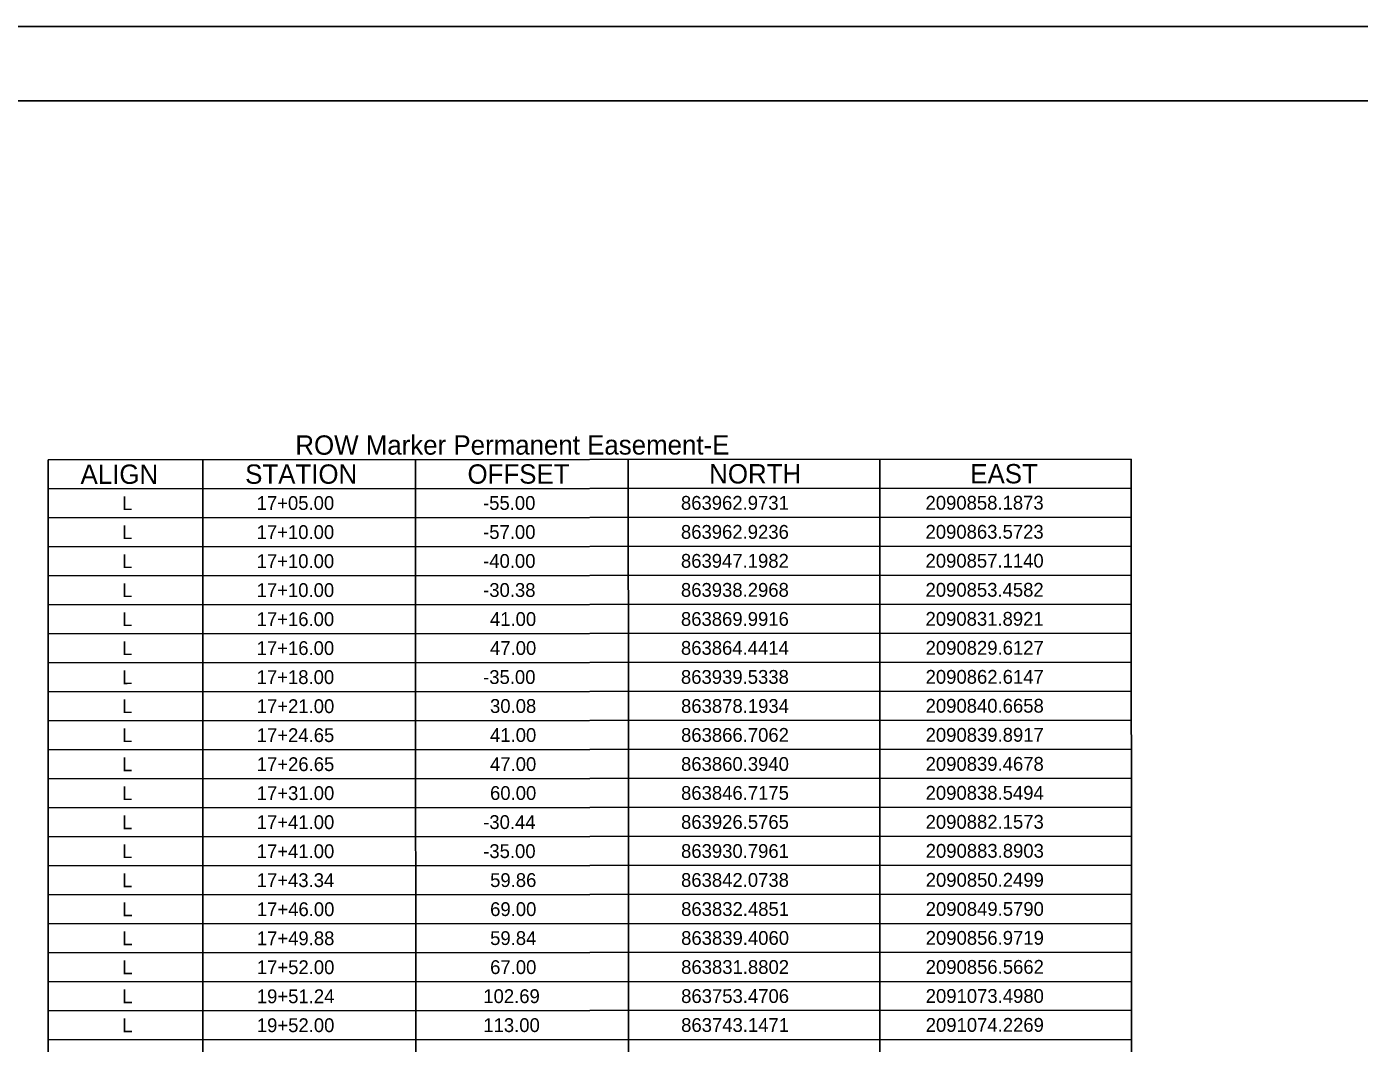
# Model space of a CAD drawing. Extents: x 2093228 to 2098328, y 861854 to 865154.
# Drawn here: x 2094038 to 2095387, y 864125 to 865154 of the extents above; entities that cross this region are included whole.
import ezdxf

# ---------------------------------------------------------------- set-up
doc = ezdxf.new("R2010")
doc.units = 0
for name, color, linetype in [('CTL Sheet Notes CELL', 7, 'Continuous'), ('CTL Sheet Table Cell', 7, 'Continuous'), ('CTL Sheet Text', 7, 'Continuous'), ('Sheet Plan CELL', 7, 'Continuous'), ('Sheet Plot Border Inside CELL', 7, 'Continuous')]:
    doc.layers.add(name, color=color, linetype=linetype)

msp = doc.modelspace()

# ---------------------------------------------------------------- linework, layer by layer
at = {"layer": 'CTL Sheet Table Cell'}
for p, q in [((2094059.8, 864715.8), (2095155.9, 864716.3)), ((2094059.8, 864715.8), (2094059.8, 864686.4)), ((2094216.3, 864715.9), (2094216.4, 864686.5)), ((2094431.7, 864716), (2094431.7, 864686.6)), ((2094647, 864716.1), (2094647, 864686.7)), ((2094901.4, 864716.2), (2094901.5, 864686.8)), ((2095155.9, 864716.3), (2095155.9, 864687)), ((2094059.8, 864686.4), (2095155.9, 864687)), ((2094059.8, 864686.4), (2094059.8, 864657.1)), ((2094216.4, 864686.5), (2094216.4, 864657.2)), ((2094431.7, 864686.6), (2094431.7, 864657.3)), ((2094647, 864686.7), (2094647, 864657.4)), ((2094901.5, 864686.8), (2094901.5, 864657.5)), ((2095155.9, 864687), (2095155.9, 864657.6)), ((2094059.8, 864657.1), (2095155.9, 864657.6)), ((2094059.8, 864657.1), (2094059.8, 864627.7)), ((2094216.4, 864657.2), (2094216.4, 864627.8)), ((2094431.7, 864657.3), (2094431.7, 864627.9)), ((2094647, 864657.4), (2094647, 864628)), ((2094901.5, 864657.5), (2094901.5, 864628.1)), ((2095155.9, 864657.6), (2095156, 864628.2)), ((2094059.8, 864627.7), (2095156, 864628.2)), ((2094059.8, 864627.7), (2094059.8, 864598.4)), ((2094216.4, 864627.8), (2094216.4, 864598.4)), ((2094431.7, 864627.9), (2094431.7, 864598.5)), ((2094647, 864628), (2094647, 864598.6)), ((2094901.5, 864628.1), (2094901.5, 864598.8)), ((2095156, 864628.2), (2095156, 864598.9)), ((2094059.8, 864598.4), (2095156, 864598.9)), ((2094059.8, 864598.4), (2094059.8, 864569)), ((2094216.4, 864598.4), (2094216.4, 864569.1)), ((2094431.7, 864598.5), (2094431.7, 864569.2)), ((2094647, 864598.6), (2094647.1, 864569.3)), ((2094901.5, 864598.8), (2094901.5, 864569.4)), ((2095156, 864598.9), (2095156, 864569.5)), ((2094059.8, 864569), (2095156, 864569.5)), ((2094059.8, 864569), (2094059.8, 864539.6)), ((2094216.4, 864569.1), (2094216.4, 864539.7)), ((2094431.7, 864569.2), (2094431.7, 864539.8)), ((2094647.1, 864569.3), (2094647.1, 864539.9)), ((2094901.5, 864569.4), (2094901.5, 864540)), ((2095156, 864569.5), (2095156, 864540.2)), ((2094059.8, 864539.6), (2095156, 864540.2)), ((2094431.7, 864539.8), (2094431.8, 864510.4)), ((2094647.1, 864539.9), (2094647.1, 864510.6)), ((2094901.5, 864540), (2094901.5, 864510.7)), ((2095156, 864540.2), (2095156, 864510.8)), ((2094059.8, 864539.6), (2094059.9, 864510.3)), ((2094216.4, 864539.7), (2094216.4, 864510.3)), ((2094059.9, 864510.3), (2095156, 864510.8)), ((2094059.9, 864510.3), (2094059.9, 864480.9)), ((2094216.4, 864510.3), (2094216.5, 864481)), ((2094431.8, 864510.4), (2094431.8, 864481.1)), ((2094647.1, 864510.6), (2094647.1, 864481.2)), ((2094901.5, 864510.7), (2094901.6, 864481.3)), ((2095156, 864510.8), (2095156, 864481.4)), ((2094059.9, 864480.9), (2095156, 864481.4)), ((2094059.9, 864480.9), (2094059.9, 864451.5)), ((2094216.5, 864481), (2094216.5, 864451.6)), ((2094431.8, 864481.1), (2094431.8, 864451.7)), ((2094647.1, 864481.2), (2094647.1, 864451.8)), ((2094901.6, 864481.3), (2094901.6, 864452)), ((2095156, 864481.4), (2095156, 864452.1)), ((2094059.9, 864451.5), (2095156, 864452.1)), ((2094059.9, 864451.5), (2094059.9, 864422.2)), ((2094216.5, 864451.6), (2094216.5, 864422.3)), ((2094431.8, 864451.7), (2094431.8, 864422.4)), ((2094647.1, 864451.8), (2094647.1, 864422.5)), ((2094901.6, 864452), (2094901.6, 864422.6)), ((2095156, 864452.1), (2095156.1, 864422.7)), ((2094059.9, 864422.2), (2095156.1, 864422.7)), ((2094059.9, 864422.2), (2094059.9, 864392.8)), ((2094216.5, 864422.3), (2094216.5, 864392.9)), ((2094431.8, 864422.4), (2094431.8, 864393)), ((2094647.1, 864422.5), (2094647.1, 864393.1)), ((2094901.6, 864422.6), (2094901.6, 864393.2)), ((2095156.1, 864422.7), (2095156.1, 864393.4)), ((2094059.9, 864392.8), (2095156.1, 864393.4)), ((2094059.9, 864392.8), (2094059.9, 864363.5)), ((2094216.5, 864392.9), (2094216.5, 864363.5)), ((2094431.8, 864393), (2094431.8, 864363.6)), ((2094647.1, 864393.1), (2094647.2, 864363.7)), ((2094901.6, 864393.2), (2094901.6, 864363.9)), ((2095156.1, 864393.4), (2095156.1, 864364)), ((2094059.9, 864363.5), (2095156.1, 864364)), ((2094059.9, 864363.5), (2094059.9, 864334.1)), ((2094216.5, 864363.5), (2094216.5, 864334.2)), ((2094431.8, 864363.6), (2094431.8, 864334.3)), ((2094647.2, 864363.7), (2094647.2, 864334.4)), ((2094901.6, 864363.9), (2094901.6, 864334.5)), ((2095156.1, 864364), (2095156.1, 864334.6)), ((2094059.9, 864334.1), (2095156.1, 864334.6)), ((2094059.9, 864334.1), (2094059.9, 864304.7)), ((2094216.5, 864334.2), (2094216.5, 864304.8)), ((2094431.8, 864334.3), (2094431.9, 864304.9)), ((2094647.2, 864334.4), (2094647.2, 864305)), ((2094901.6, 864334.5), (2094901.6, 864305.1)), ((2095156.1, 864334.6), (2095156.1, 864305.3)), ((2094059.9, 864304.7), (2095156.1, 864305.3)), ((2094059.9, 864304.7), (2094060, 864275.4)), ((2094216.5, 864304.8), (2094216.6, 864275.5)), ((2094431.9, 864304.9), (2094431.9, 864275.6)), ((2094647.2, 864305), (2094647.2, 864275.7)), ((2094901.6, 864305.1), (2094901.7, 864275.8)), ((2095156.1, 864305.3), (2095156.1, 864275.9)), ((2094060, 864275.4), (2095156.1, 864275.9)), ((2094060, 864275.4), (2094060, 864246)), ((2094216.6, 864275.5), (2094216.6, 864246.1)), ((2094431.9, 864275.6), (2094431.9, 864246.2)), ((2094647.2, 864275.7), (2094647.2, 864246.3)), ((2094901.7, 864275.8), (2094901.7, 864246.4)), ((2095156.1, 864275.9), (2095156.1, 864246.5)), ((2094060, 864246), (2095156.1, 864246.5)), ((2094060, 864246), (2094060, 864216.7)), ((2094216.6, 864246.1), (2094216.6, 864216.7)), ((2094431.9, 864246.2), (2094431.9, 864216.8)), ((2094647.2, 864246.3), (2094647.2, 864216.9)), ((2094901.7, 864246.4), (2094901.7, 864217.1)), ((2095156.1, 864246.5), (2095156.2, 864217.2)), ((2094060, 864216.7), (2095156.2, 864217.2)), ((2094060, 864216.7), (2094060, 864187.3)), ((2094216.6, 864216.7), (2094216.6, 864187.4)), ((2094431.9, 864216.8), (2094431.9, 864187.5)), ((2094647.2, 864216.9), (2094647.2, 864187.6)), ((2094901.7, 864217.1), (2094901.7, 864187.7)), ((2095156.2, 864217.2), (2095156.2, 864187.8)), ((2094060, 864187.3), (2095156.2, 864187.8)), ((2094060, 864187.3), (2094060, 864157.9)), ((2094216.6, 864187.4), (2094216.6, 864158)), ((2094431.9, 864187.5), (2094431.9, 864158.1)), ((2094647.2, 864187.6), (2094647.3, 864158.2)), ((2094901.7, 864187.7), (2094901.7, 864158.3)), ((2095156.2, 864187.8), (2095156.2, 864158.5)), ((2094060, 864157.9), (2095156.2, 864158.5)), ((2094060, 864157.9), (2094060, 864128.6)), ((2094216.6, 864158), (2094216.6, 864128.6)), ((2094431.9, 864158.1), (2094431.9, 864128.7)), ((2094647.3, 864158.2), (2094647.3, 864128.9)), ((2094901.7, 864158.3), (2094901.7, 864129)), ((2095156.2, 864158.5), (2095156.2, 864129.1)), ((2094060, 864128.6), (2095156.2, 864129.1)), ((2094060, 864128.6), (2094060, 864099.2)), ((2094216.6, 864128.6), (2094216.6, 864099.3)), ((2094431.9, 864128.7), (2094432, 864099.4)), ((2094647.3, 864128.9), (2094647.3, 864099.5)), ((2094901.7, 864129), (2094901.7, 864099.6)), ((2095156.2, 864129.1), (2095156.2, 864099.7))]:
    msp.add_line(p, q, dxfattribs=at)
at = {"layer": 'Sheet Plan CELL'}
msp.add_lwpolyline([(2093753.4, 865079.1), (2098253.4, 865079.1), (2098253.4, 861929.1), (2093753.4, 861929.1)], close=True, dxfattribs=at)
at = {"layer": 'Sheet Plot Border Inside CELL'}
msp.add_lwpolyline([(2098328.4, 865154.1), (2093228.4, 865154.1), (2093228.4, 861854.1), (2098328.4, 861854.1)], close=True, dxfattribs=at)

# ---------------------------------------------------------------- texts
at = {"layer": 'CTL Sheet Notes CELL'}
for s, height, p in [('ROW Marker Permanent Easement-E', 19.574, (2094310.1, 864720.8)), ('ALIGN', 19.57, (2094092.7, 864691.3)), ('STATION', 19.57, (2094259.3, 864691.4)), ('OFFSET', 19.57, (2094484.3, 864691.5)), ('NORTH', 19.57, (2094728.9, 864691.7)), ('EAST', 19.57, (2094993.1, 864691.8))]:
    msp.add_text(s, height=height, rotation=0.0276, dxfattribs=at).set_placement(p)
at = {"layer": 'CTL Sheet Text'}
for s, height, p in [('L', 14, (2094134.7, 864664.8)), ('17+05.00', 13.98, (2094270.9, 864664.9)), ('-55.00', 13.98, (2094500, 864665)), ('863962.9731', 13.982, (2094700.3, 864665.1)), ('2090858.1873', 13.982, (2094947.8, 864665.2)), ('L', 14, (2094134.7, 864635.4)), ('17+10.00', 13.98, (2094270.9, 864635.5)), ('-57.00', 13.98, (2094500.1, 864635.6)), ('863962.9236', 13.982, (2094700.3, 864635.7)), ('2090863.5723', 13.982, (2094947.8, 864635.8)), ('2090857.1140', 13.982, (2094947.8, 864606.5)), ('L', 14, (2094134.7, 864606.1)), ('17+10.00', 13.98, (2094270.9, 864606.1)), ('-40.00', 13.98, (2094500.1, 864606.3)), ('863947.1982', 13.982, (2094700.3, 864606.4)), ('L', 14, (2094134.7, 864576.7)), ('17+10.00', 13.98, (2094270.9, 864576.8)), ('-30.38', 13.98, (2094500.1, 864576.9)), ('863938.2968', 13.982, (2094700.3, 864577)), ('2090853.4582', 13.982, (2094947.8, 864577.1)), ('L', 14, (2094134.7, 864547.4)), ('17+16.00', 13.98, (2094270.9, 864547.4)), ('41.00', 13.98, (2094507, 864547.5)), ('863869.9916', 13.982, (2094700.3, 864547.6)), ('2090831.8921', 13.982, (2094947.8, 864547.7)), ('L', 14, (2094134.7, 864518)), ('17+16.00', 13.98, (2094270.9, 864518.1)), ('47.00', 13.98, (2094507.1, 864518.2)), ('863864.4414', 13.982, (2094700.3, 864518.3)), ('2090829.6127', 13.982, (2094947.9, 864518.4)), ('L', 14, (2094134.7, 864488.6)), ('17+18.00', 13.98, (2094270.9, 864488.7)), ('-35.00', 13.98, (2094500.1, 864488.8)), ('863939.5338', 13.982, (2094700.3, 864488.9)), ('2090862.6147', 13.982, (2094947.9, 864489)), ('L', 14, (2094134.8, 864459.3)), ('17+21.00', 13.98, (2094271, 864459.3)), ('30.08', 13.98, (2094507.1, 864459.5)), ('863878.1934', 13.982, (2094700.4, 864459.5)), ('2090840.6658', 13.982, (2094947.9, 864459.7)), ('L', 14, (2094134.8, 864429.9)), ('17+24.65', 13.98, (2094271, 864430)), ('41.00', 13.98, (2094507.1, 864430.1)), ('863866.7062', 13.982, (2094700.4, 864430.2)), ('2090839.8917', 13.982, (2094947.9, 864430.3)), ('L', 14, (2094134.8, 864400.5)), ('17+26.65', 13.98, (2094271, 864400.6)), ('47.00', 13.98, (2094507.1, 864400.7)), ('863860.3940', 13.982, (2094700.4, 864400.8)), ('2090839.4678', 13.982, (2094947.9, 864400.9)), ('L', 14, (2094134.8, 864371.2)), ('17+31.00', 13.98, (2094271, 864371.3)), ('60.00', 13.98, (2094507.1, 864371.4)), ('863846.7175', 13.982, (2094700.4, 864371.5)), ('2090838.5494', 13.982, (2094947.9, 864371.6)), ('L', 14, (2094134.8, 864341.8)), ('17+41.00', 13.98, (2094271, 864341.9)), ('-30.44', 13.98, (2094500.2, 864342)), ('863926.5765', 13.982, (2094700.4, 864342.1)), ('2090882.1573', 13.982, (2094947.9, 864342.2)), ('L', 14, (2094134.8, 864312.5)), ('17+41.00', 13.98, (2094271, 864312.5)), ('-35.00', 13.98, (2094500.2, 864312.6)), ('863930.7961', 13.982, (2094700.4, 864312.7)), ('2090883.8903', 13.982, (2094948, 864312.9)), ('L', 14, (2094134.8, 864283.1)), ('17+43.34', 13.98, (2094271, 864283.2)), ('59.86', 13.98, (2094507.2, 864283.3)), ('863842.0738', 13.982, (2094700.4, 864283.4)), ('2090850.2499', 13.982, (2094948, 864283.5)), ('L', 14, (2094134.9, 864253.7)), ('17+46.00', 13.98, (2094271.1, 864253.8)), ('69.00', 13.98, (2094507.2, 864253.9)), ('863832.4851', 13.982, (2094700.5, 864254)), ('2090849.5790', 13.982, (2094948, 864254.1)), ('L', 14, (2094134.9, 864224.4)), ('17+49.88', 13.98, (2094271.1, 864224.4)), ('59.84', 13.98, (2094507.2, 864224.6)), ('863839.4060', 13.982, (2094700.5, 864224.7)), ('2090856.9719', 13.982, (2094948, 864224.8)), ('L', 14, (2094134.9, 864195)), ('17+52.00', 13.98, (2094271.1, 864195.1)), ('67.00', 13.98, (2094507.2, 864195.2)), ('863831.8802', 13.982, (2094700.5, 864195.3)), ('2090856.5662', 13.982, (2094948, 864195.4)), ('L', 14, (2094134.9, 864165.7)), ('19+51.24', 13.98, (2094271.1, 864165.7)), ('102.69', 13.98, (2094500.3, 864165.8)), ('863753.4706', 13.982, (2094700.5, 864165.9)), ('2091073.4980', 13.982, (2094948, 864166)), ('L', 14, (2094134.9, 864136.3)), ('19+52.00', 13.98, (2094271.1, 864136.4)), ('113.00', 13.98, (2094500.3, 864136.5)), ('863743.1471', 13.982, (2094700.5, 864136.6)), ('2091074.2269', 13.982, (2094948, 864136.7))]:
    msp.add_text(s, height=height, rotation=0.0276, dxfattribs=at).set_placement(p)

doc.saveas('drawing.dxf')
